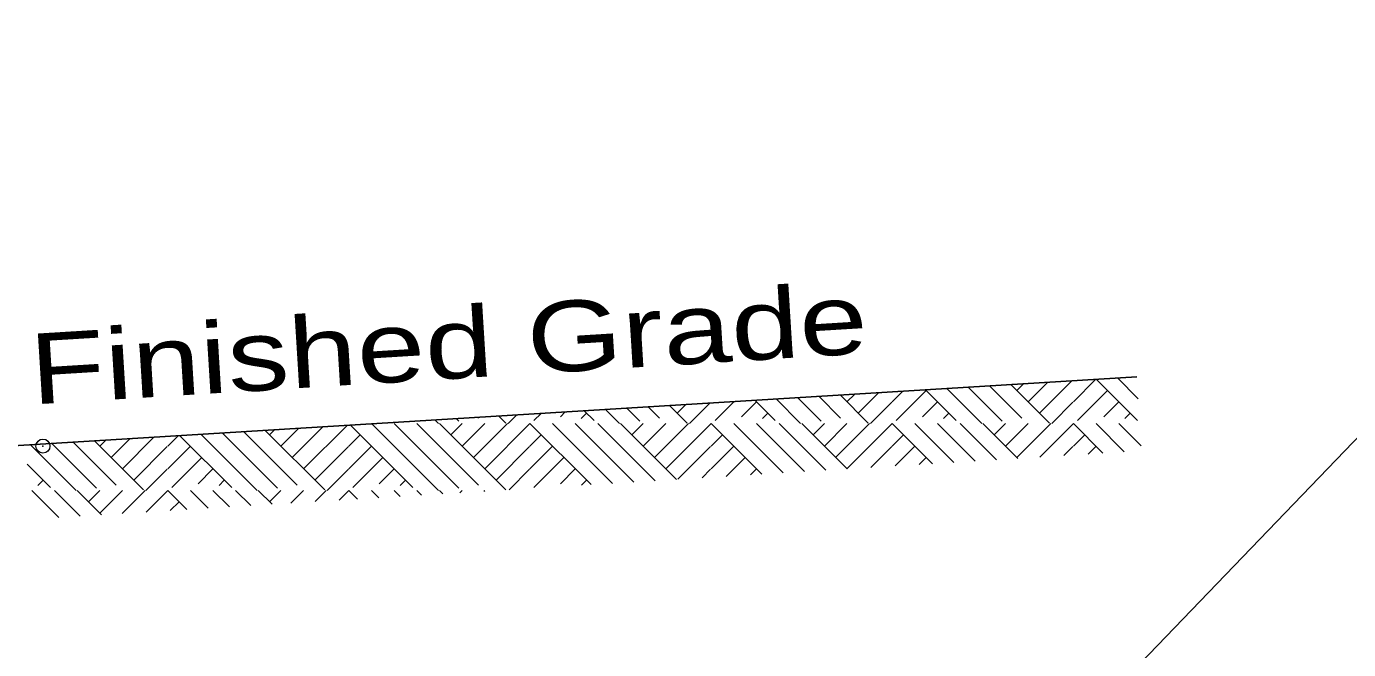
# Model space of a CAD drawing. Extents: x 1083.1 to 1117.1, y 697.4 to 741.4.
# Drawn here: x 1098.05 to 1100.973, y 707.345 to 708.723 of the extents above; entities that cross this region are included whole.
import ezdxf
from ezdxf.enums import TextEntityAlignment as Align

# ---------------------------------------------------------------- set-up
doc = ezdxf.new("R2010")
doc.units = 0
doc.header["$LTSCALE"] = 0.062
doc.header["$PDMODE"] = 32
doc.header["$PDSIZE"] = 0.031
doc.layers.add('1', color=7, linetype='Continuous', lineweight=13)

msp = doc.modelspace()

# ---------------------------------------------------------------- linework, layer by layer
at = {"layer": '1', "lineweight": 25}
msp.add_line((1100.50475, 707.9485), (1097.77125, 707.78017), dxfattribs=at)
at = {"layer": '1'}
for p, q in [((1099.97292, 707.85175), (1100.03917, 707.91808)), ((1100.03758, 707.91975), (1100.10567, 707.85158)), ((1100.08458, 707.92267), (1100.162, 707.84525)), ((1100.13183, 707.92558), (1100.20708, 707.85025)), ((1100.17908, 707.9285), (1100.25042, 707.85708)), ((1100.22617, 707.93142), (1100.31142, 707.84608)), ((1100.23942, 707.91808), (1100.25442, 707.93308)), ((1100.26442, 707.89308), (1100.30775, 707.93642)), ((1100.28942, 707.86808), (1100.36108, 707.93975)), ((1100.36458, 707.893), (1100.4145, 707.94292)), ((1100.37342, 707.85175), (1100.43967, 707.91808)), ((1100.41475, 707.943), (1100.50617, 707.85158)), ((1100.46192, 707.94583), (1100.50775, 707.9)), ((1099.51558, 707.845), (1099.561, 707.89042)), ((1099.57242, 707.85175), (1099.61433, 707.89367)), ((1099.63075, 707.86008), (1099.66375, 707.89308)), ((1099.66025, 707.8965), (1099.70517, 707.85158)), ((1099.70742, 707.89942), (1099.7615, 707.84525)), ((1099.7545, 707.90233), (1099.80658, 707.85025)), ((1099.80175, 707.90525), (1099.84992, 707.85708)), ((1099.84892, 707.90817), (1099.91092, 707.84608)), ((1099.86392, 707.89308), (1099.881, 707.91017)), ((1099.88892, 707.86808), (1099.93425, 707.91333)), ((1099.91608, 707.845), (1099.96308, 707.892)), ((1099.96408, 707.893), (1099.98775, 707.91667)), ((1100.03125, 707.86008), (1100.06425, 707.89308)), ((1100.31658, 707.845), (1100.36358, 707.892)), ((1100.43175, 707.86008), (1100.46475, 707.89308)), ((1099.09433, 707.86167), (1099.10992, 707.84608)), ((1099.11508, 707.845), (1099.13425, 707.86417)), ((1099.17192, 707.85175), (1099.18758, 707.86742)), ((1099.23025, 707.86008), (1099.24083, 707.87067)), ((1099.2765, 707.85633), (1099.28825, 707.86808)), ((1099.28308, 707.87325), (1099.30467, 707.85158)), ((1099.33008, 707.87617), (1099.361, 707.84525)), ((1099.37733, 707.87908), (1099.40608, 707.85025)), ((1099.4245, 707.882), (1099.44942, 707.85708)), ((1099.47158, 707.88492), (1099.51042, 707.84608)), ((1099.4885, 707.86808), (1099.5075, 707.88708)), ((1099.677, 707.85633), (1099.68875, 707.86808)), ((1100.0775, 707.85633), (1100.08925, 707.86808)), ((1100.478, 707.85633), (1100.48975, 707.86808)), ((1098.58742, 707.82), (1098.59858, 707.83117)), ((1098.61242, 707.795), (1098.65192, 707.83442)), ((1098.63742, 707.77), (1098.70525, 707.83767)), ((1098.6625, 707.74492), (1098.75858, 707.841)), ((1098.76617, 707.8415), (1098.90417, 707.70342)), ((1098.81325, 707.84442), (1098.9605, 707.69708)), ((1098.86267, 707.845), (1099.00558, 707.70217)), ((1098.91283, 707.845), (1099.04892, 707.70892)), ((1098.95283, 707.85292), (1098.9605, 707.84525)), ((1098.96292, 707.845), (1099.10967, 707.69825)), ((1098.98792, 707.82), (1099.01292, 707.845)), ((1099, 707.85583), (1099.00558, 707.85025)), ((1099.01292, 707.795), (1099.063, 707.845)), ((1099.03792, 707.77), (1099.11308, 707.845)), ((1099.04725, 707.85875), (1099.04892, 707.85708)), ((1099.06292, 707.74492), (1099.16308, 707.845)), ((1099.16308, 707.845), (1099.29825, 707.70983)), ((1099.21317, 707.845), (1099.34542, 707.71267)), ((1099.26317, 707.845), (1099.39267, 707.71558)), ((1099.31333, 707.845), (1099.43983, 707.7185)), ((1099.36342, 707.845), (1099.487, 707.72142)), ((1099.38842, 707.82), (1099.41342, 707.845)), ((1099.41342, 707.795), (1099.4635, 707.845)), ((1099.43842, 707.77), (1099.51358, 707.845)), ((1099.46342, 707.74492), (1099.56358, 707.845)), ((1099.56358, 707.845), (1099.6755, 707.73308)), ((1099.61358, 707.845), (1099.72267, 707.736)), ((1099.66367, 707.845), (1099.76983, 707.73892)), ((1099.71383, 707.845), (1099.81708, 707.74183)), ((1099.76383, 707.845), (1099.86417, 707.74467)), ((1099.78892, 707.82), (1099.81392, 707.845)), ((1099.81392, 707.795), (1099.864, 707.845)), ((1099.83892, 707.77), (1099.91408, 707.845)), ((1099.86392, 707.74492), (1099.96408, 707.845)), ((1099.96408, 707.845), (1100.05283, 707.75625)), ((1100.01408, 707.845), (1100.09992, 707.75917)), ((1100.06417, 707.845), (1100.14708, 707.76208)), ((1100.11433, 707.845), (1100.19433, 707.765)), ((1100.16433, 707.845), (1100.24142, 707.76792)), ((1100.18942, 707.82), (1100.21442, 707.845)), ((1100.21442, 707.795), (1100.2645, 707.845)), ((1100.23942, 707.77), (1100.3145, 707.845)), ((1100.2905, 707.77092), (1100.36458, 707.845)), ((1100.36458, 707.845), (1100.43, 707.77958)), ((1100.41458, 707.845), (1100.47717, 707.7825)), ((1100.46467, 707.845), (1100.51417, 707.7955)), ((1098.15317, 707.80367), (1098.248, 707.70892)), ((1098.20033, 707.80658), (1098.30892, 707.698)), ((1098.21192, 707.795), (1098.22508, 707.80808)), ((1098.23692, 707.77), (1098.2785, 707.81142)), ((1098.262, 707.74492), (1098.33175, 707.81475)), ((1098.36208, 707.795), (1098.38517, 707.818)), ((1098.38892, 707.81817), (1098.50375, 707.70342)), ((1098.43608, 707.82108), (1098.56, 707.69708)), ((1098.48317, 707.824), (1098.60508, 707.70217)), ((1098.53042, 707.82692), (1098.64842, 707.70892)), ((1098.57758, 707.82983), (1098.70942, 707.698)), ((1098.76258, 707.795), (1098.78758, 707.82)), ((1099.16308, 707.795), (1099.18808, 707.82)), ((1099.56358, 707.795), (1099.58858, 707.82)), ((1099.96408, 707.795), (1099.98908, 707.82)), ((1100.36458, 707.795), (1100.38958, 707.82)), ((1098.05875, 707.79792), (1098.15958, 707.69708)), ((1098.10592, 707.80083), (1098.20458, 707.70217)), ((1098.287, 707.71992), (1098.36108, 707.794)), ((1098.36208, 707.74483), (1098.41225, 707.795)), ((1098.6875, 707.71992), (1098.76158, 707.794)), ((1098.76258, 707.74483), (1098.81275, 707.795)), ((1099.088, 707.71992), (1099.16208, 707.794)), ((1099.16308, 707.74483), (1099.21317, 707.795)), ((1099.49017, 707.72167), (1099.56258, 707.794)), ((1099.56358, 707.74483), (1099.61367, 707.795)), ((1099.91692, 707.74792), (1099.96308, 707.794)), ((1099.97042, 707.75125), (1100.01417, 707.795)), ((1100.34375, 707.77417), (1100.36358, 707.794)), ((1100.39725, 707.7775), (1100.41467, 707.795)), ((1098.05167, 707.75492), (1098.10325, 707.70342)), ((1098.31408, 707.69692), (1098.36108, 707.74383)), ((1098.37092, 707.70367), (1098.43725, 707.77)), ((1098.42925, 707.71192), (1098.46225, 707.74492)), ((1098.71458, 707.69692), (1098.76158, 707.74383)), ((1098.77142, 707.70367), (1098.83775, 707.77)), ((1098.82975, 707.71192), (1098.86275, 707.74492)), ((1099.11692, 707.69867), (1099.16208, 707.74383)), ((1099.17192, 707.70367), (1099.23825, 707.77)), ((1099.23025, 707.71192), (1099.26325, 707.74492)), ((1099.54367, 707.725), (1099.56258, 707.74383)), ((1099.59692, 707.72817), (1099.63875, 707.77)), ((1099.65033, 707.7315), (1099.66375, 707.74492)), ((1100.02375, 707.7545), (1100.03917, 707.77)), ((1098.07508, 707.70817), (1098.08675, 707.71992)), ((1098.47558, 707.70817), (1098.48725, 707.71992)), ((1098.87608, 707.70817), (1098.88775, 707.71992)), ((1099.27692, 707.7085), (1099.28825, 707.71992)), ((1098.06167, 707.69692), (1098.12125, 707.63733)), ((1098.11183, 707.69692), (1098.1685, 707.64025)), ((1098.16192, 707.69692), (1098.21567, 707.64317)), ((1098.18692, 707.67183), (1098.21192, 707.69692)), ((1098.21192, 707.64675), (1098.26208, 707.69692)), ((1098.26117, 707.646), (1098.31208, 707.69692)), ((1098.31442, 707.64917), (1098.36208, 707.69692)), ((1098.36208, 707.69692), (1098.40417, 707.65483)), ((1098.41217, 707.69692), (1098.45142, 707.65767)), ((1098.46217, 707.69692), (1098.4985, 707.6605)), ((1098.51233, 707.69692), (1098.54583, 707.66342)), ((1098.56242, 707.69692), (1098.59292, 707.66633)), ((1098.58742, 707.67183), (1098.61242, 707.69692)), ((1098.63458, 707.66892), (1098.6625, 707.69692)), ((1098.68792, 707.67225), (1098.71258, 707.69692)), ((1098.74117, 707.6755), (1098.76258, 707.69692)), ((1098.76258, 707.69692), (1098.7815, 707.678)), ((1098.81267, 707.69692), (1098.82858, 707.68092)), ((1098.86267, 707.69692), (1098.87575, 707.68383)), ((1098.91283, 707.69692), (1098.923, 707.68675)), ((1098.96292, 707.69692), (1098.97008, 707.68967)), ((1099.008, 707.69192), (1099.01292, 707.69692)), ((1099.06133, 707.69525), (1099.063, 707.69692)), ((1098.36775, 707.6525), (1098.38717, 707.67183))]:
    msp.add_line(p, q, dxfattribs=at)
msp.add_lwpolyline([(1099.87325, 706.64992), (1101.86758, 708.7235), (1102.3145, 708.7235)], dxfattribs=at)
msp.add_point((1098.08633, 707.79508), dxfattribs=at)

# ---------------------------------------------------------------- texts
at = {"layer": '1', "width": 1.3}
msp.add_text('Finished Grade', height=0.156, rotation=3.524, dxfattribs=at).set_placement((1098.98779, 707.94406), align=Align.CENTER)

doc.saveas('drawing.dxf')
